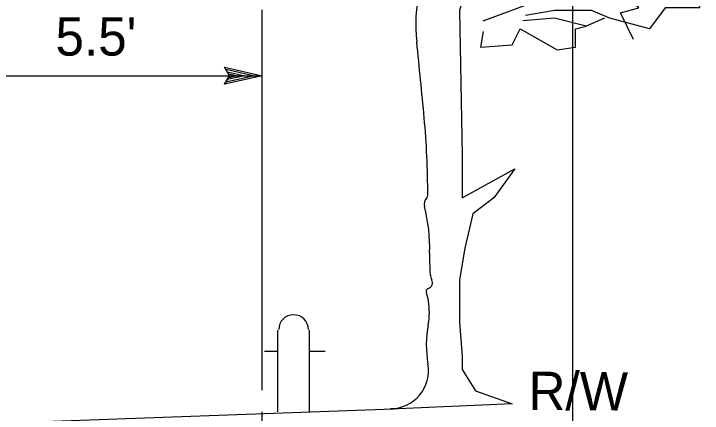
# Model space of a CAD drawing. Extents: x -119017 to -116080, y -104449 to -102845.
# Drawn here: x -118213.6 to -118105.7, y -103126.6 to -103064.1 of the extents above; entities that cross this region are included whole.
import ezdxf

# ---------------------------------------------------------------- set-up
doc = ezdxf.new("R2010")
doc.units = 0
for name, color, linetype in [('G-MARK', 7, 'Continuous'), ('G-TEXT', 7, 'Continuous'), ('Misc CnstDet(22)', 7, 'Continuous')]:
    doc.layers.add(name, color=color, linetype=linetype)

msp = doc.modelspace()

# ---------------------------------------------------------------- linework, layer by layer
at = {"layer": 'G-MARK'}
for p, q in [((-118174.72, -103123.01), (-118174.72, -103063.48)), ((-118229.29, -103073.82), (-118174.72, -103073.82))]:
    msp.add_line(p, q, dxfattribs=at)
at = {"layer": 'G-TEXT'}
msp.add_lwpolyline([(-118180.63, -103072.5), (-118174.72, -103073.82), (-118180.63, -103075.13), (-118180.42, -103074.78), (-118176.09, -103073.82), (-118180.42, -103072.85), (-118180.21, -103073.2), (-118177.44, -103073.82), (-118180.21, -103074.43), (-118180, -103074.08), (-118178.8, -103073.82), (-118180, -103073.55), (-118179.84, -103073.82), (-118180.63, -103075.13), (-118179.84, -103073.82)], close=True, dxfattribs=at)
at = {"layer": 'Misc CnstDet(22)'}
for p, q in [((-118125.99, -103240.93), (-118125.99, -102921.38)), ((-118125.58, -103066.48), (-118123.92, -103066.07)), ((-118174.72, -103073.82), (-118174.72, -103073.82)), ((-118172.29, -103113.61), (-118172.29, -103126.42)), ((-118167.33, -103113.61), (-118167.33, -103126.42)), ((-118174.35, -103116.91), (-118172.29, -103116.91)), ((-118167.33, -103116.91), (-118164.85, -103116.91)), ((-118154.1, -103126.01), (-118223.96, -103128.49)), ((-118174.77, -103126.42), (-118174.77, -103133.04)), ((-118174.72, -103126.32), (-118174.72, -103126.32))]:
    msp.add_line(p, q, dxfattribs=at)
for points in [[(-118131.36, -103051.6), (-118142.11, -103057.8), (-118143.76, -103063.59), (-118143.35, -103086.32), (-118143.35, -103092.94), (-118135.08, -103088.39), (-118138.39, -103092.94), (-118141.7, -103095.42), (-118142.94, -103100.79), (-118143.76, -103105.75), (-118143.76, -103112.37), (-118143.35, -103117.74), (-118143.35, -103118.57), (-118143.35, -103119.81), (-118141.28, -103123.11), (-118135.5, -103125.18)], [(-118116.48, -103068.13), (-118118.55, -103064), (-118115.65, -103063.17), (-118120.2, -103059.45), (-118114.83, -103058.21), (-118116.48, -103054.49), (-118122.27, -103052.01), (-118128.06, -103051.6), (-118131.36, -103051.6)], [(-118105.73, -103053.25), (-118106.97, -103055.73), (-118106.15, -103063.17), (-118111.52, -103063.17), (-118114, -103066.48), (-118120.2, -103064.83), (-118123.09, -103063.59), (-118128.88, -103063.59), (-118133.43, -103064.41)], [(-118140.04, -103065.24), (-118133.43, -103062.76), (-118137.15, -103061.52), (-118129.3, -103061.11), (-118119.37, -103057.39), (-118117.72, -103056.15)], [(-118121.03, -103064.83), (-118123.92, -103066.07), (-118128.88, -103064.83), (-118133.84, -103065.24)], [(-118140.04, -103066.89), (-118140.46, -103069.37), (-118135.5, -103068.96), (-118134.26, -103066.48), (-118128.47, -103069.79), (-118125.58, -103069.37), (-118125.58, -103066.48)], [(-118135.5, -103125.18), (-118154.51, -103126.01)]]:
    msp.add_lwpolyline(points, dxfattribs=at)
for centre, radius, start, end in [((-118124.85, -103065.8), 25.78, 168.2081, 186.0646), ((-118947.91, -103153.25), 801.92, 5.21154, 6.06457), ((-118286.78, -103092.94), 138.04, 0.1692, 5.2115), ((-118147.93, -103093.91), 1.39, 133.9804, 194.8085), ((-118149.26, -103092.54), 0.517, 313.9804, 0.1692), ((-118173.54, -103100.69), 25.1, 358.0391, 14.8085), ((-118120.62, -103102.5), 27.85, 178.0391, 184.938), ((-118148.93, -103106.2), 0.928, 287.5823, 28.3771), ((-118146.15, -103104.7), 2.23, 184.938, 208.3771), ((-118148.51, -103107.54), 0.471, 107.5823, 195.6375), ((-118162.16, -103111.36), 13.7, 9.4308, 15.6375), ((-118158.86, -103110.81), 10.36, 349.2955, 9.4308), ((-118169.78, -103113.55), 2.33, 0, 180), ((-118131.68, -103115.94), 17.3, 169.2955, 189.9787), ((-118154.56, -103119.97), 5.93, 269.7971, 9.9787)]:
    msp.add_arc(centre, radius, start, end, dxfattribs=at)

# ---------------------------------------------------------------- texts
msp.add_text("5.5'", height=6, dxfattribs=at).set_placement((-118207.09, -103070.67))
msp.add_text('R/W', height=6, rotation=359.6007, dxfattribs=at).set_placement((-118132.98, -103126.11))

doc.saveas('drawing.dxf')
